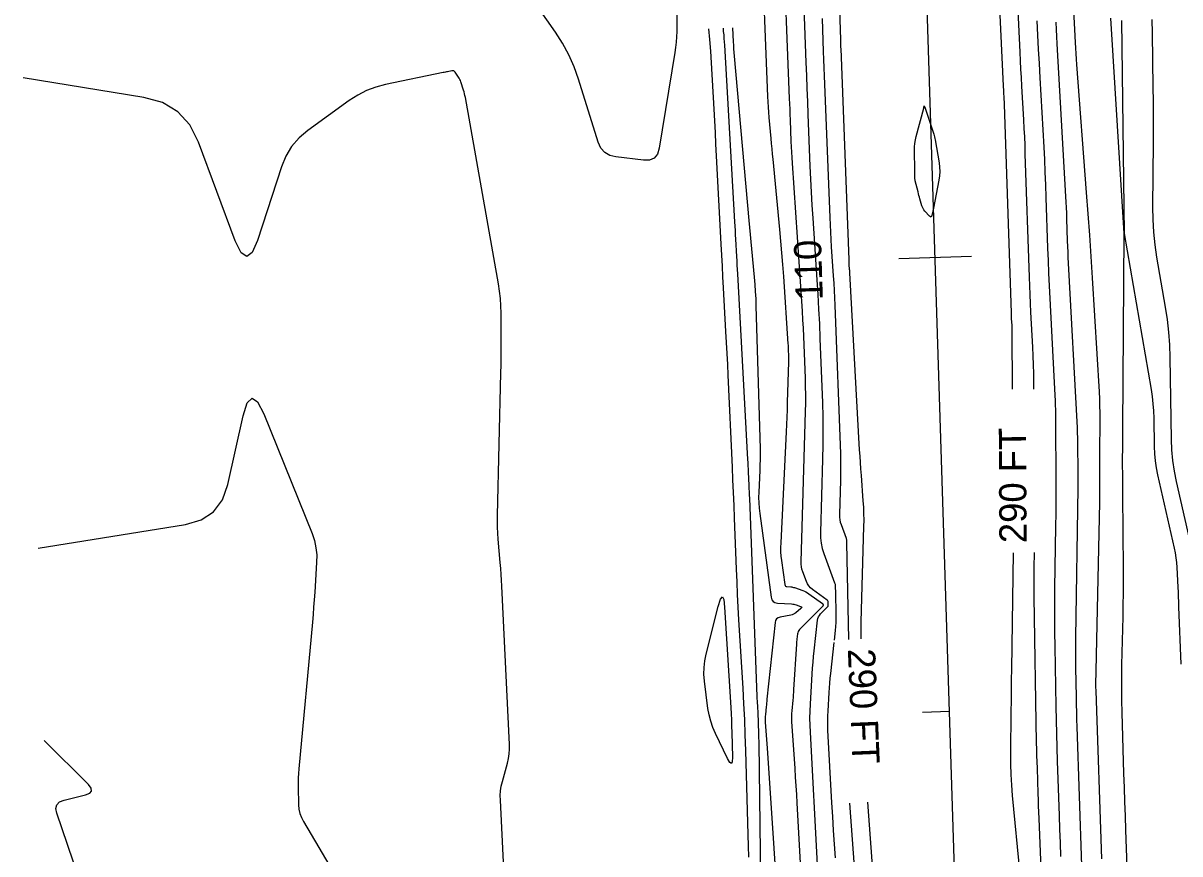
# Model space of a CAD drawing. Extents: x 1768942 to 1774819, y 723037 to 732099.
# Drawn here: x 1770607 to 1770861.8, y 725105.6 to 725288.6 of the extents above; entities that cross this region are included whole.
import ezdxf

# ---------------------------------------------------------------- set-up
doc = ezdxf.new("R2010")
doc.units = 0
for name, color, linetype in [('R_Contour Annot', 7, 'Continuous'), ('R_Contours', 7, 'Continuous'), ('R_Horz Alg', 7, 'Continuous'), ('R_Horz Alg Annot', 7, 'Continuous')]:
    doc.layers.add(name, color=color, linetype=linetype)

msp = doc.modelspace()

# ---------------------------------------------------------------- linework, layer by layer
at = {"layer": 'R_Contours'}
for points in [[(1770791.56, 725152.97), (1770791.57, 725154.53), (1770791.62, 725156.75), (1770792.2, 725177.75), (1770792.22, 725179.16), (1770792.21, 725180.56), (1770792.15, 725181.97), (1770792.06, 725183.37), (1770791.63, 725188.99), (1770791.52, 725190.4), (1770791.43, 725191.81), (1770791.34, 725193.21), (1770791.25, 725194.62), (1770789.09, 725233.56), (1770789.09, 725233.62), (1770789.09, 725233.67), (1770789.08, 725233.73), (1770789.08, 725233.79), (1770789.07, 725234.01), (1770789.06, 725234.06), (1770789.06, 725234.12), (1770789.06, 725234.17), (1770789.05, 725234.23), (1770788.98, 725235.53), (1770788.97, 725235.77), (1770788.96, 725236), (1770788.95, 725236.24), (1770788.94, 725236.47), (1770787.16, 725282.96), (1770787.15, 725283.13), (1770787.15, 725283.3), (1770787.14, 725283.47), (1770787.13, 725283.64), (1770787.11, 725284.31), (1770787.1, 725284.48), (1770787.09, 725284.65), (1770787.09, 725284.82), (1770787.08, 725284.99), (1770785.47, 725332.57)], [(1770750.99, 725291.35), (1770750.96, 725286.7), (1770750.93, 725285.54), (1770750.85, 725284.38), (1770750.73, 725283.23), (1770750.57, 725282.08), (1770747.12, 725261.03), (1770746.72, 725259.74), (1770746, 725258.87), (1770744.97, 725258.42), (1770743.62, 725258.39), (1770737.59, 725259.11), (1770736.22, 725259.45), (1770735.11, 725260.1), (1770734.26, 725261.07), (1770733.68, 725262.36), (1770729.36, 725276.23), (1770728.39, 725278.98), (1770727.22, 725281.62), (1770725.84, 725284.17), (1770724.26, 725286.61), (1770706.05, 725312.54)], [(1770821.07, 725312.28), (1770822.87, 725274.73), (1770822.89, 725274.39), (1770822.91, 725274.05), (1770822.93, 725273.71), (1770822.94, 725273.37), (1770823.02, 725272.01), (1770823.04, 725271.67), (1770823.06, 725271.33), (1770823.07, 725270.99), (1770823.08, 725270.65), (1770824.61, 725224.8), (1770824.62, 725224.45), (1770824.63, 725224.11), (1770824.65, 725223.77), (1770824.66, 725223.43), (1770824.74, 725222.06), (1770824.75, 725221.72), (1770824.77, 725221.38), (1770824.77, 725221.04), (1770824.78, 725220.7), (1770824.86, 725207.96)], [(1770829.63, 725207.99), (1770829.62, 725209.48), (1770829.6, 725211.41), (1770829.55, 725213.35), (1770829.49, 725215.28), (1770829.39, 725217.21), (1770828.98, 725224.94), (1770828.88, 725226.87), (1770828.79, 725228.8), (1770828.71, 725230.73), (1770828.64, 725232.66), (1770827.74, 725259.8), (1770827.68, 725261.67), (1770827.6, 725263.53), (1770827.51, 725265.39), (1770827.41, 725267.26), (1770826.99, 725274.71), (1770826.88, 725276.57), (1770826.79, 725278.43), (1770826.69, 725280.29), (1770826.6, 725282.16), (1770825.13, 725312.71)], [(1770769.58, 725307.9), (1770770.97, 725272.4), (1770771.02, 725271.25), (1770771.09, 725270.1), (1770771.17, 725268.94), (1770771.27, 725267.79), (1770771.68, 725263.19), (1770771.78, 725262.04), (1770771.89, 725260.89), (1770771.99, 725259.74), (1770772.11, 725258.59), (1770773.61, 725243.14), (1770773.85, 725240.56), (1770774.07, 725237.98), (1770774.28, 725235.4), (1770774.46, 725232.81), (1770775.46, 725217.97), (1770775.48, 725217.64), (1770775.5, 725217.31), (1770775.52, 725216.98), (1770775.53, 725216.64), (1770775.58, 725215.31), (1770775.59, 725214.98), (1770775.59, 725214.65), (1770775.59, 725214.32), (1770775.58, 725213.98), (1770775.32, 725205), (1770775.27, 725203.39), (1770775.21, 725201.79), (1770775.14, 725200.18), (1770775.07, 725198.57), (1770773.87, 725174.1), (1770773.84, 725173.14), (1770773.86, 725172.17), (1770773.93, 725171.22), (1770774.03, 725170.26), (1770774.76, 725164.93), (1770774.82, 725164.75), (1770774.91, 725164.61), (1770775.05, 725164.53), (1770775.24, 725164.49), (1770776.08, 725164.44), (1770776.29, 725164.42), (1770776.5, 725164.38), (1770776.7, 725164.33), (1770776.9, 725164.27), (1770778.72, 725163.65), (1770779.08, 725163.51), (1770779.43, 725163.34), (1770779.76, 725163.15), (1770780.08, 725162.93), (1770783.1, 725160.75), (1770783.14, 725160.71), (1770783.17, 725160.67), (1770783.18, 725160.63), (1770783.19, 725160.58), (1770783.2, 725160.37), (1770783.19, 725160.32), (1770783.18, 725160.28), (1770783.16, 725160.24), (1770783.13, 725160.2), (1770778.01, 725155.02), (1770777.83, 725154.82), (1770777.7, 725154.59), (1770777.61, 725154.34), (1770777.55, 725154.07), (1770777.43, 725152.95), (1770777.4, 725152.68), (1770777.38, 725152.4), (1770777.35, 725152.12), (1770777.34, 725151.84), (1770776.72, 725141.81), (1770776.68, 725141.23), (1770776.64, 725140.65), (1770776.59, 725140.07), (1770776.53, 725139.48), (1770776.29, 725137.15), (1770776.25, 725136.57), (1770776.23, 725135.99), (1770776.23, 725135.41), (1770776.26, 725134.82), (1770776.96, 725124.48), (1770777.08, 725122.56), (1770777.2, 725120.64), (1770777.32, 725118.72), (1770777.43, 725116.8), (1770778.94, 725089.19)], [(1770782, 725103.25), (1770780.4, 725132.46), (1770780.34, 725134), (1770780.32, 725135.54), (1770780.35, 725137.08), (1770780.42, 725138.61), (1770780.83, 725145.3), (1770780.91, 725146.57), (1770781.02, 725147.83), (1770781.13, 725149.09), (1770781.26, 725150.35), (1770782.01, 725157.11), (1770782.08, 725157.49), (1770782.21, 725157.85), (1770782.4, 725158.17), (1770782.66, 725158.47), (1770784.14, 725159.97), (1770784.23, 725160.08), (1770784.29, 725160.2), (1770784.33, 725160.34), (1770784.34, 725160.48), (1770784.32, 725161.07), (1770784.3, 725161.21), (1770784.25, 725161.33), (1770784.18, 725161.44), (1770784.07, 725161.54), (1770780.84, 725163.88), (1770780.41, 725164.24), (1770780.04, 725164.65), (1770779.75, 725165.11), (1770779.52, 725165.63), (1770778.73, 725167.77), (1770778.56, 725168.31), (1770778.44, 725168.86), (1770778.38, 725169.42), (1770778.37, 725169.98), (1770779.33, 725203.04), (1770779.37, 725204.88), (1770779.38, 725206.72), (1770779.36, 725208.56), (1770779.3, 725210.4), (1770779.03, 725217.76), (1770778.95, 725219.59), (1770778.86, 725221.43), (1770778.76, 725223.27), (1770778.64, 725225.11), (1770776.44, 725257.77), (1770776.37, 725258.95), (1770776.3, 725260.14), (1770776.24, 725261.32), (1770776.19, 725262.5), (1770776.01, 725267.24), (1770775.97, 725268.43), (1770775.92, 725269.61), (1770775.87, 725270.8), (1770775.83, 725271.98), (1770774.4, 725307.9)], [(1770778.79, 725296.12), (1770779.44, 725279.88), (1770779.55, 725277.03), (1770779.66, 725274.18), (1770779.77, 725271.32), (1770779.88, 725268.47), (1770780.32, 725257.05), (1770780.44, 725254.19), (1770780.58, 725251.34), (1770780.74, 725248.49), (1770780.92, 725245.64), (1770781.84, 725232.01), (1770782.04, 725228.78), (1770782.22, 725225.56), (1770782.38, 725222.33), (1770782.52, 725219.11), (1770783.05, 725204.97), (1770783.14, 725201.88), (1770783.17, 725198.78), (1770783.16, 725195.69), (1770783.1, 725192.59), (1770782.62, 725176.43), (1770782.64, 725175.24), (1770782.78, 725174.07), (1770783.02, 725172.91), (1770783.38, 725171.78), (1770785.74, 725165.36), (1770785.8, 725165.19), (1770785.84, 725165.02), (1770785.87, 725164.84), (1770785.88, 725164.66), (1770785.9, 725163.94), (1770785.91, 725163.76), (1770785.91, 725163.58), (1770785.92, 725163.4), (1770785.92, 725163.22), (1770786.03, 725158.33), (1770786.03, 725157.45), (1770786.01, 725156.58), (1770785.95, 725155.71), (1770785.87, 725154.83), (1770785.64, 725152.73)], [(1770844.61, 725104.55), (1770843.32, 725141.53), (1770843.31, 725141.6), (1770843.31, 725141.67), (1770843.31, 725141.74), (1770843.31, 725141.81), (1770843.3, 725142.1), (1770843.3, 725142.17), (1770843.3, 725142.24), (1770843.3, 725142.31), (1770843.3, 725142.38), (1770843.36, 725146.52), (1770843.38, 725147.24), (1770843.39, 725147.95), (1770843.4, 725148.67), (1770843.42, 725149.38), (1770844.15, 725182.98), (1770844.17, 725183.88), (1770844.18, 725184.77), (1770844.18, 725185.66), (1770844.18, 725186.56), (1770844.15, 725190.13), (1770844.15, 725191.02), (1770844.15, 725191.92), (1770844.15, 725192.81), (1770844.15, 725193.7), (1770844.21, 725201.21), (1770844.21, 725202.76), (1770844.18, 725204.31), (1770844.13, 725205.85), (1770844.05, 725207.4), (1770842.52, 725232.51), (1770842.23, 725237.21), (1770841.92, 725241.91), (1770841.59, 725246.61), (1770841.24, 725251.3), (1770839.12, 725279.43), (1770839.03, 725280.64), (1770838.95, 725281.86), (1770838.87, 725283.07), (1770838.8, 725284.28), (1770838.4, 725291.41)], [(1770782.97, 725289.57), (1770783.26, 725282.35), (1770783.33, 725280.54), (1770783.4, 725278.74), (1770783.47, 725276.93), (1770783.54, 725275.13), (1770784.67, 725245.76), (1770784.74, 725244.15), (1770784.82, 725242.55), (1770784.91, 725240.94), (1770785.01, 725239.33), (1770785.44, 725232.9), (1770785.54, 725231.29), (1770785.63, 725229.68), (1770785.71, 725228.08), (1770785.78, 725226.47), (1770787.01, 725193.76), (1770787.05, 725192.3), (1770787.07, 725190.85), (1770787.06, 725189.4), (1770787.03, 725187.94), (1770786.81, 725180.34), (1770786.82, 725179.78), (1770786.88, 725179.23), (1770787, 725178.69), (1770787.16, 725178.16), (1770788.27, 725175.14), (1770788.3, 725175.06), (1770788.32, 725174.98), (1770788.33, 725174.9), (1770788.34, 725174.81), (1770788.35, 725174.47), (1770788.35, 725174.39), (1770788.35, 725174.3), (1770788.36, 725174.22), (1770788.36, 725174.13), (1770788.81, 725152.86)], [(1770835.59, 725105.08), (1770835.48, 725108.08), (1770835.37, 725111.08), (1770835.26, 725114.08), (1770834.84, 725126.09), (1770834.74, 725129.09), (1770834.66, 725132.09), (1770834.58, 725135.09), (1770834.53, 725138.09), (1770834.3, 725151.29), (1770834.26, 725154.49), (1770834.24, 725157.69), (1770834.25, 725160.89), (1770834.28, 725164.09), (1770834.48, 725177.84), (1770834.52, 725180.59), (1770834.53, 725183.33), (1770834.54, 725186.08), (1770834.53, 725188.83), (1770834.46, 725199.82), (1770834.43, 725202.57), (1770834.36, 725205.31), (1770834.26, 725208.06), (1770834.13, 725210.8), (1770833.22, 725227.93), (1770833.07, 725230.71), (1770832.95, 725233.49), (1770832.83, 725236.27), (1770832.73, 725239.05), (1770832.36, 725250.17), (1770832.26, 725252.95), (1770832.15, 725255.74), (1770832.01, 725258.51), (1770831.86, 725261.29), (1770831, 725276.56), (1770830.83, 725279.69), (1770830.66, 725282.81), (1770830.5, 725285.94), (1770830.35, 725289.06)], [(1770834.44, 725288.8), (1770834.53, 725287.19), (1770834.61, 725285.59), (1770834.7, 725283.98), (1770836.6, 725250.38), (1770836.67, 725249.16), (1770836.72, 725247.94), (1770836.78, 725246.72), (1770836.82, 725245.5), (1770836.98, 725240.61), (1770837.03, 725239.39), (1770837.08, 725238.17), (1770837.13, 725236.95), (1770837.19, 725235.73), (1770839.13, 725199.49), (1770839.19, 725198.39), (1770839.23, 725197.28), (1770839.25, 725196.18), (1770839.27, 725195.07), (1770839.29, 725190.65), (1770839.3, 725189.55), (1770839.3, 725188.45), (1770839.29, 725187.34), (1770839.28, 725186.24), (1770838.79, 725153.23), (1770838.78, 725151.6), (1770838.77, 725149.96), (1770838.78, 725148.33), (1770838.8, 725146.69), (1770838.91, 725140.15), (1770838.95, 725138.52), (1770838.98, 725136.88), (1770839.03, 725135.25), (1770839.08, 725133.61), (1770840.15, 725103.11)], [(1770850.54, 725092.7), (1770849.89, 725110.9), (1770849.78, 725114.01), (1770849.67, 725117.13), (1770849.57, 725120.24), (1770849.47, 725123.36), (1770849.07, 725136.8), (1770849.01, 725139.43), (1770848.98, 725142.05), (1770848.98, 725144.68), (1770849.03, 725147.3), (1770849.26, 725157.81), (1770849.3, 725160.44), (1770849.33, 725163.06), (1770849.34, 725165.69), (1770849.33, 725168.32), (1770849.21, 725184.78), (1770849.19, 725188.4), (1770849.18, 725192.02), (1770849.19, 725195.64), (1770849.21, 725199.25), (1770849.53, 725242.24), (1770849.53, 725242.25), (1770846.61, 725289.63)], [(1770848.96, 725289.17), (1770849.53, 725242.25), (1770849.53, 725242.24), (1770855.45, 725207.87), (1770855.69, 725206.32), (1770855.86, 725204.75), (1770855.98, 725203.19), (1770856.03, 725201.61), (1770856.13, 725195.31), (1770856.19, 725193.74), (1770856.34, 725192.18), (1770856.56, 725190.63), (1770856.87, 725189.08), (1770860.52, 725172.97), (1770860.73, 725171.91), (1770860.9, 725170.85), (1770861.03, 725169.78), (1770861.1, 725168.7), (1770861.32, 725164.38), (1770861.37, 725163.3), (1770861.42, 725162.22), (1770861.47, 725161.14), (1770861.51, 725160.06), (1770861.99, 725147.39)], [(1770855.64, 725289.38), (1770855.71, 725286.38), (1770855.86, 725274.36), (1770855.89, 725271.35), (1770855.9, 725268.35), (1770855.9, 725265.34), (1770855.88, 725262.34), (1770855.75, 725248.08), (1770855.79, 725245.3), (1770855.95, 725242.53), (1770856.24, 725239.77), (1770856.65, 725237.02), (1770858.54, 725226.04), (1770858.96, 725223.29), (1770859.27, 725220.53), (1770859.47, 725217.76), (1770859.57, 725214.98), (1770859.84, 725196.92), (1770859.94, 725194.58), (1770860.16, 725192.26), (1770860.49, 725189.95), (1770860.95, 725187.66), (1770863.8, 725175.06)], [(1770766.83, 725104.95), (1770766.77, 725107.4), (1770766.71, 725109.84), (1770766.19, 725128.39), (1770766.08, 725131.83), (1770765.94, 725135.27), (1770765.78, 725138.71), (1770765.58, 725142.14), (1770764.68, 725157.15), (1770764.52, 725159.96), (1770764.38, 725162.76), (1770764.25, 725165.56), (1770764.13, 725168.37), (1770763.71, 725179.59), (1770763.6, 725182.39), (1770763.48, 725185.2), (1770763.36, 725188), (1770763.24, 725190.81), (1770762.31, 725211.02), (1770762.2, 725213.43), (1770762.08, 725215.83), (1770761.95, 725218.24), (1770761.82, 725220.64), (1770761.29, 725230.26), (1770761.16, 725232.67), (1770761.03, 725235.07), (1770760.9, 725237.48), (1770760.78, 725239.89), (1770759.76, 725259.38), (1770759.62, 725261.93), (1770759.48, 725264.49), (1770759.34, 725267.05), (1770759.19, 725269.6), (1770758.61, 725279.83), (1770758.45, 725282.38), (1770758.26, 725284.93), (1770758.05, 725287.34)], [(1770769.58, 725094.03), (1770769.11, 725130.03), (1770769.1, 725130.57), (1770769.09, 725131.11), (1770769.08, 725131.65), (1770769.06, 725132.18), (1770769, 725134.43), (1770768.98, 725134.92), (1770768.97, 725135.41), (1770768.94, 725135.9), (1770768.91, 725136.38), (1770768.8, 725138.33), (1770768.77, 725138.82), (1770768.74, 725139.31), (1770768.72, 725139.8), (1770768.7, 725140.28), (1770767.05, 725183.94), (1770767.02, 725184.65), (1770766.99, 725185.37), (1770766.96, 725186.08), (1770766.93, 725186.8), (1770766.8, 725189.66), (1770766.77, 725190.37), (1770766.73, 725191.09), (1770766.69, 725191.8), (1770766.65, 725192.52), (1770764.4, 725233.37), (1770764.35, 725234.33), (1770764.3, 725235.28), (1770764.25, 725236.24), (1770764.2, 725237.2), (1770764, 725241.02), (1770763.94, 725241.98), (1770763.89, 725242.93), (1770763.84, 725243.89), (1770763.79, 725244.84), (1770761.56, 725283.71), (1770761.51, 725284.47), (1770761.45, 725285.22), (1770761.39, 725285.98), (1770761.31, 725286.73), (1770761.24, 725287.46)], [(1770763.28, 725287.53), (1770763.4, 725284.48), (1770763.44, 725283.69), (1770763.48, 725282.9), (1770763.54, 725282.11), (1770763.61, 725281.33), (1770766.84, 725245.13), (1770766.98, 725243.56), (1770767.12, 725242), (1770767.27, 725240.43), (1770767.42, 725238.86), (1770768.03, 725232.6), (1770768.17, 725231.03), (1770768.28, 725229.46), (1770768.37, 725227.89), (1770768.43, 725226.32), (1770769.32, 725194.84), (1770769.34, 725193.65), (1770769.34, 725192.46), (1770769.31, 725191.27), (1770769.27, 725190.08), (1770769.03, 725185.31), (1770769, 725184.13), (1770769.03, 725182.94), (1770769.1, 725181.75), (1770769.24, 725180.57), (1770771.77, 725162.14), (1770771.91, 725161.61), (1770772.19, 725161.22), (1770772.6, 725160.97), (1770773.14, 725160.86), (1770776.26, 725160.67), (1770776.51, 725160.64), (1770776.76, 725160.6), (1770777.01, 725160.54), (1770777.26, 725160.47), (1770778.23, 725160.13), (1770778.42, 725160.04), (1770778.5, 725159.92), (1770778.47, 725159.79), (1770778.32, 725159.64), (1770777.22, 725158.74), (1770776.96, 725158.55), (1770776.68, 725158.4), (1770776.39, 725158.29), (1770776.08, 725158.21), (1770773.72, 725157.79), (1770773.28, 725157.65), (1770772.95, 725157.41), (1770772.73, 725157.06), (1770772.62, 725156.61), (1770770.84, 725139.7), (1770770.8, 725139.28), (1770770.76, 725138.86), (1770770.71, 725138.44), (1770770.67, 725138.02), (1770770.5, 725136.35), (1770770.47, 725135.93), (1770770.45, 725135.51), (1770770.45, 725135.09), (1770770.47, 725134.67), (1770770.86, 725128.93), (1770770.94, 725127.83), (1770771.01, 725126.74), (1770771.09, 725125.64), (1770771.16, 725124.54), (1770773.55, 725089.23)], [(1770714, 725079.55), (1770712.13, 725117.45), (1770712.12, 725118.5), (1770712.19, 725119.53), (1770712.34, 725120.56), (1770712.58, 725121.58), (1770713.7, 725125.63), (1770713.94, 725126.64), (1770714.09, 725127.67), (1770714.16, 725128.71), (1770714.15, 725129.75), (1770712.44, 725164.58), (1770712.37, 725165.88), (1770712.29, 725167.18), (1770712.2, 725168.47), (1770712.1, 725169.77), (1770711.67, 725174.96), (1770711.59, 725176.26), (1770711.53, 725177.55), (1770711.51, 725178.85), (1770711.52, 725180.15), (1770712.26, 725211.59), (1770712.3, 725213.22), (1770712.32, 725214.86), (1770712.33, 725216.49), (1770712.33, 725218.13), (1770712.3, 725224.67), (1770712.26, 725226.3), (1770712.15, 725227.93), (1770711.97, 725229.55), (1770711.72, 725231.16), (1770704.42, 725272.18), (1770704.34, 725272.6), (1770704.24, 725273), (1770704.14, 725273.41), (1770704.02, 725273.81), (1770703.45, 725275.65), (1770703.35, 725275.93), (1770703.23, 725276.19), (1770703.09, 725276.45), (1770702.93, 725276.7), (1770702.19, 725277.76), (1770702.04, 725277.93), (1770701.86, 725278.03), (1770701.66, 725278.08), (1770701.44, 725278.06), (1770700.5, 725277.87), (1770700.26, 725277.82), (1770700.03, 725277.78), (1770699.79, 725277.73), (1770699.56, 725277.68), (1770686.87, 725275.05), (1770684.72, 725274.49), (1770682.67, 725273.71), (1770680.71, 725272.72), (1770678.85, 725271.51), (1770669.76, 725264.94), (1770667.8, 725263.29), (1770666.17, 725261.4), (1770664.87, 725259.27), (1770663.9, 725256.9), (1770658.64, 725240.72), (1770657.48, 725238.07), (1770656.28, 725237.17), (1770655.04, 725238.02), (1770653.76, 725240.62), (1770645.66, 725262.36), (1770643.73, 725266.14), (1770641.09, 725269.04), (1770637.73, 725271.07), (1770633.65, 725272.22), (1770607.03, 725276.53)], [(1770610.37, 725172.94), (1770642.8, 725178.17), (1770646.25, 725179.18), (1770648.96, 725180.99), (1770650.91, 725183.59), (1770652.12, 725186.98), (1770655.47, 725202.13), (1770656.38, 725204.99), (1770657.45, 725206.01), (1770658.67, 725205.18), (1770660.04, 725202.51), (1770670.65, 725176.19), (1770671.17, 725174.65), (1770671.52, 725173.07), (1770671.68, 725171.47), (1770671.67, 725169.84), (1770671.24, 725163.25), (1770671.13, 725161.61), (1770671.01, 725159.96), (1770670.87, 725158.32), (1770670.73, 725156.68), (1770667.73, 725124.34), (1770667.65, 725123.36), (1770667.61, 725122.38), (1770667.59, 725121.39), (1770667.6, 725120.41), (1770667.7, 725116.47), (1770667.78, 725115.5), (1770667.99, 725114.57), (1770668.31, 725113.67), (1770668.75, 725112.81), (1770687.9, 725080.38)], [(1770825.04, 725171.96), (1770824.69, 725146.3), (1770824.66, 725143.98), (1770824.63, 725141.66), (1770824.6, 725139.34), (1770824.58, 725137.02), (1770824.47, 725127.74), (1770824.47, 725125.42), (1770824.54, 725123.11), (1770824.67, 725120.79), (1770824.86, 725118.48), (1770826.51, 725101.21)], [(1770832.2, 725078.55), (1770830.79, 725113.41), (1770830.73, 725114.8), (1770830.68, 725116.19), (1770830.63, 725117.57), (1770830.58, 725118.96), (1770830.39, 725124.52), (1770830.34, 725125.91), (1770830.3, 725127.3), (1770830.27, 725128.69), (1770830.24, 725130.08), (1770829.69, 725162.21), (1770829.67, 725163.81), (1770829.66, 725165.41), (1770829.66, 725167.01), (1770829.68, 725168.62), (1770829.73, 725171.99)], [(1770785.58, 725152.2), (1770784.83, 725145.33), (1770784.72, 725144.3), (1770784.62, 725143.27), (1770784.54, 725142.23), (1770784.47, 725141.2), (1770784.22, 725137.06), (1770784.17, 725136.02), (1770784.15, 725134.98), (1770784.16, 725133.95), (1770784.2, 725132.91), (1770785.09, 725116.86), (1770785.26, 725113.84), (1770785.45, 725110.82), (1770785.65, 725107.8), (1770785.86, 725104.78)], [(1770628.79, 725072.58), (1770614.45, 725114.59), (1770614.26, 725115.64), (1770614.45, 725116.47), (1770615.05, 725117.08), (1770616.04, 725117.47), (1770620.78, 725118.62), (1770621.71, 725118.98), (1770622.12, 725119.48), (1770622.03, 725120.13), (1770621.42, 725120.91), (1770611.66, 725130.59)], [(1770789.02, 725116.83), (1770791.16, 725087.79)], [(1770795.49, 725084.04), (1770793.05, 725117)]]:
    msp.add_lwpolyline(points, dxfattribs=at)
for points in [[(1770807.67, 725263.8), (1770807.75, 725263.5), (1770807.82, 725263.2), (1770807.88, 725262.89), (1770808.75, 725257.81), (1770808.87, 725256.86), (1770808.91, 725255.91), (1770808.85, 725254.96), (1770808.71, 725254.02), (1770807.51, 725247.84), (1770807.5, 725247.84), (1770807.5, 725247.84), (1770807.5, 725247.84), (1770807.5, 725247.84), (1770807.5, 725247.85), (1770807.49, 725247.85), (1770807.49, 725247.85), (1770807.49, 725247.85), (1770807.49, 725247.85), (1770807.16, 725246.19), (1770807.09, 725245.97), (1770806.99, 725245.87), (1770806.85, 725245.9), (1770806.67, 725246.05), (1770805.64, 725247.17), (1770805.42, 725247.44), (1770805.23, 725247.72), (1770805.08, 725248.03), (1770804.97, 725248.35), (1770804.52, 725249.9), (1770804.41, 725250.27), (1770804.31, 725250.64), (1770804.21, 725251.01), (1770804.12, 725251.39), (1770803.49, 725253.86), (1770803.45, 725254.05), (1770803.42, 725254.23), (1770803.4, 725254.42), (1770803.39, 725254.61), (1770803.39, 725255.37), (1770803.39, 725255.56), (1770803.38, 725255.75), (1770803.38, 725255.94), (1770803.38, 725256.13), (1770803.34, 725260.51), (1770803.35, 725261.3), (1770803.42, 725262.09), (1770803.55, 725262.87), (1770803.72, 725263.64), (1770805.36, 725269.87), (1770805.38, 725269.92), (1770805.39, 725269.98), (1770805.4, 725270.04), (1770805.41, 725270.09), (1770805.46, 725270.35), (1770805.47, 725270.38), (1770805.47, 725270.39), (1770805.48, 725270.39), (1770805.49, 725270.36), (1770805.53, 725270.2), (1770805.54, 725270.16), (1770805.55, 725270.12), (1770805.56, 725270.08), (1770805.58, 725270.05), (1770807.57, 725264.1)], [(1770762.93, 725136.5), (1770763, 725135.13), (1770763.05, 725133.77), (1770763.1, 725132.4), (1770763.25, 725126.94), (1770763.21, 725125.9), (1770763.01, 725125.51), (1770762.65, 725125.76), (1770762.14, 725126.67), (1770759.5, 725132.13), (1770758.92, 725133.47), (1770758.45, 725134.84), (1770758.1, 725136.24), (1770757.85, 725137.68), (1770757.08, 725143.71), (1770756.96, 725145.19), (1770756.98, 725146.67), (1770757.15, 725148.14), (1770757.45, 725149.6), (1770760.12, 725160.08), (1770760.63, 725161.75), (1770761.04, 725162.28), (1770761.34, 725161.68), (1770761.53, 725159.95), (1770762.86, 725137.86)]]:
    msp.add_lwpolyline(points, close=True, dxfattribs=at)
at = {"layer": 'R_Horz Alg'}
msp.add_line((1770821.12, 724822.68), (1770798.66, 725525.31), dxfattribs=at)
msp.add_line((1770821.12, 724822.68), (1770798.66, 725525.31), dxfattribs=at)
for points in [[(1770799.88, 725236.76), (1770815.87, 725237.27)], [(1770805.07, 725136.88), (1770811.07, 725137.07)]]:
    msp.add_lwpolyline(points, dxfattribs=at)

# ---------------------------------------------------------------- texts
at = {"layer": 'R_Contour Annot'}
for rotation, p in [(90.2862, (1770828.03, 725174.08)), (272.3724, (1770788.65, 725150.75))]:
    msp.add_text('290 FT', height=6, rotation=rotation, dxfattribs=at).set_placement(p)
at = {"layer": 'R_Horz Alg Annot'}
msp.add_text('110', height=6, rotation=91.8304, dxfattribs=at).set_placement((1770783.17, 725227.58))

doc.saveas('drawing.dxf')
